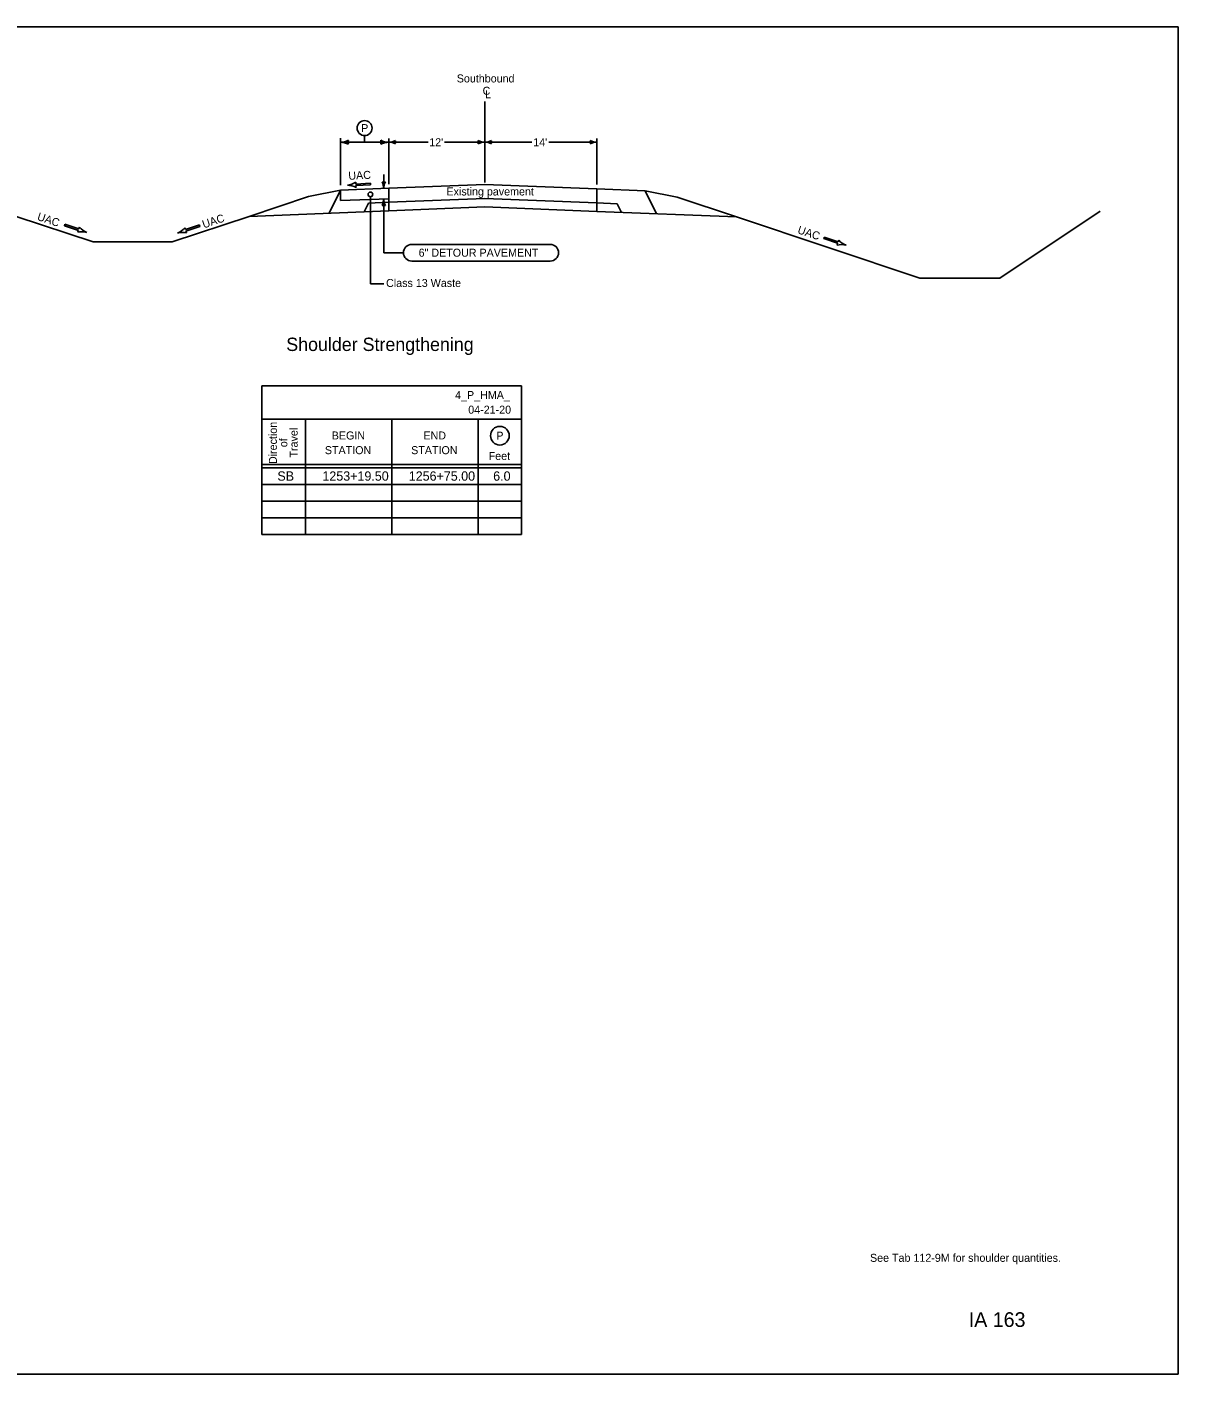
# Model space of a CAD drawing. Extents: x 10133 to 81668, y 7924 to 11018.
# Drawn here: x 11541 to 13268, y 7924 to 9944 of the extents above; entities that cross this region are included whole.
import ezdxf

# ---------------------------------------------------------------- set-up
doc = ezdxf.new("R2010")
doc.units = 0
for name, color, linetype in [('dsnCellElements', 7, 'Continuous'), ('dsnCellsNorthArrow', 7, 'Continuous'), ('DsnShtRevisedText', 7, 'Continuous'), ('dsnStdNameDate', 7, 'Continuous'), ('dsnStdTable', 7, 'Continuous'), ('dsnTextFinalPlan', 7, 'Continuous'), ('dsnTextTabulation', 7, 'Continuous'), ('dsnXsPCCPavementBottom', 7, 'Continuous'), ('dsnXsShldrEarthFill', 7, 'Continuous'), ('dsnXsShldrSpecialBackBottom', 7, 'Continuous'), ('Level 6', 7, 'Continuous'), ('Level 7', 7, 'Continuous'), ('Level 8', 7, 'Continuous'), ('SheetAddendum', 7, 'Continuous'), ('SheetBorder', 7, 'Continuous')]:
    doc.layers.add(name, color=color, linetype=linetype)

# ---------------------------------------------------------------- blocks, each defined once
blk = doc.blocks.new('LT')
at = {"layer": 'dsnCellsNorthArrow'}
for centre, radius, start, end in [((-35.6, 0), 16.4, 342.2666, 17.7333), ((0, 42.5), 42.5, 241.9275, 270), ((0, -42.5), 42.5, 90, 118.0725)]:
    blk.add_arc(centre, radius, start, end, dxfattribs=at)

msp = doc.modelspace()

# ---------------------------------------------------------------- linework, layer by layer
at = {"layer": 'DsnShtRevisedText'}
for p, q in [((12022, 9706.6), (12022, 9706.6)), ((12034.5, 9711.3), (12034.7, 9708.5)), ((12034.7, 9708.5), (12056.7, 9709.7)), ((12056.8, 9707.3), (12034.8, 9706.1)), ((12034.8, 9706.1), (12035, 9703.3)), ((12056.7, 9709.7), (12056.8, 9707.3)), ((12056.4, 9558.7), (12056.4, 9689.4)), ((12326.2, 9618), (12118.6, 9618)), ((12118.6, 9618), (12326.2, 9618)), ((12118.6, 9593), (12326.2, 9593)), ((12118.6, 9593), (12326.2, 9593)), ((12076.7, 9558.7), (12056.4, 9558.7))]:
    msp.add_line(p, q, dxfattribs=at)
msp.add_circle((12056.4, 9692.9), 3.5, dxfattribs=at)
for centre, radius, start, end in [((12019.5, 9732.3), 25.8, 275.5881, 305.6181), ((12022.4, 9680.8), 25.8, 60.854, 90.8841), ((12118.6, 9605.5), 12.5, 90, 270), ((12118.6, 9605.5), 12.5, 90, 270), ((12326.2, 9605.5), 12.5, 270, 90), ((12326.2, 9605.5), 12.5, 270, 90)]:
    msp.add_arc(centre, radius, start, end, dxfattribs=at)
at = {"layer": 'dsnStdNameDate'}
for p, q in [((12084, 9702.1), (12011.6, 9699.2)), ((12011.6, 9699.2), (12011.6, 9683.6)), ((12084, 9702.1), (12084, 9686.4)), ((12084, 9686.4), (12011.6, 9683.6))]:
    msp.add_line(p, q, dxfattribs=at)
at = {"layer": 'dsnStdTable'}
for p, q in [((11893.9, 9183.1), (11893.9, 9406.1)), ((11893.9, 9406.1), (12283.2, 9406.1)), ((12283.2, 9183.1), (12283.2, 9406.1)), ((11893.9, 9356.1), (12283.2, 9356.1)), ((11959.2, 9183.1), (11959.2, 9356.1)), ((12088.6, 9356.1), (12088.6, 9183.1)), ((12218.2, 9183.1), (12218.2, 9356.1)), ((11893.9, 9288.1), (12283.2, 9288.1)), ((11893.9, 9283.1), (12283.2, 9283.1)), ((11893.9, 9258.1), (12283.2, 9258.1)), ((11893.9, 9233.1), (12283.2, 9233.1)), ((11893.9, 9208.1), (12283.2, 9208.1)), ((11893.9, 9183.1), (12283.2, 9183.1))]:
    msp.add_line(p, q, dxfattribs=at)
at = {"layer": 'dsnTextFinalPlan'}
for p, q in [((12011.6, 9699.2), (12084, 9702.1)), ((12011.6, 9683.6), (12011.6, 9699.2)), ((12084, 9702.1), (12084, 9686.4)), ((12084, 9686.4), (12011.6, 9683.6))]:
    msp.add_line(p, q, dxfattribs=at)
at = {"layer": 'dsnXsPCCPavementBottom'}
for p, q in [((12084.1, 9668.4), (12084.1, 9702.1)), ((12396.1, 9667.4), (12396.1, 9701.1)), ((12084.1, 9668.4), (11874.9, 9660)), ((12396.1, 9667.4), (12605.2, 9659.1))]:
    msp.add_line(p, q, dxfattribs=at)
at = {"layer": 'dsnXsShldrEarthFill'}
for p, q in [((12011.6, 9699.2), (11963.6, 9689.6)), ((12468.5, 9698.2), (12516.5, 9688.6)), ((11963.6, 9689.6), (11874.9, 9660)), ((12516.5, 9688.6), (12605.2, 9659.1)), ((11525.2, 9660), (11641, 9621.9)), ((11874.9, 9660), (11759.1, 9621.9)), ((12605.2, 9659.1), (12880.2, 9567.4)), ((13000.2, 9567.4), (13150.7, 9667.7)), ((11598.5, 9648.2), (11597.8, 9645.9)), ((11597.8, 9645.9), (11618.7, 9638.9)), ((11619.4, 9641.2), (11598.5, 9648.2)), ((11618.7, 9638.9), (11617.8, 9636.3)), ((11620.3, 9643.9), (11619.4, 9641.2)), ((11631.1, 9636), (11631.1, 9636)), ((11778.2, 9642.8), (11779.1, 9640.2)), ((11779.1, 9640.2), (11800, 9647.1)), ((11800.7, 9644.8), (11779.9, 9637.9)), ((11779.9, 9637.9), (11780.7, 9635.2)), ((11800, 9647.1), (11800.7, 9644.8)), ((11640.9, 9621.9), (11759.1, 9621.9)), ((11767.4, 9635), (11767.4, 9635)), ((12737, 9628.8), (12736.3, 9626.6)), ((12736.3, 9626.6), (12757.1, 9619.6)), ((12757.9, 9621.9), (12737, 9628.8)), ((12757.1, 9619.6), (12756.2, 9616.9)), ((12758.8, 9624.5), (12757.9, 9621.9)), ((12769.6, 9616.7), (12769.6, 9616.7)), ((13000.2, 9567.4), (12880.2, 9567.4))]:
    msp.add_line(p, q, dxfattribs=at)
for centre, start, end in [((11624, 9611.2), 73.917, 103.947), ((11640.3, 9660.1), 219.183, 249.213), ((11758.2, 9659.1), 290.787, 320.817), ((11774.5, 9610.2), 76.053, 106.083), ((12762.5, 9591.9), 73.917, 103.947), ((12778.8, 9640.8), 219.183, 249.213)]:
    msp.add_arc(centre, 25.8, start, end, dxfattribs=at)
at = {"layer": 'dsnXsShldrSpecialBackBottom'}
for p, q in [((12053.6, 9679.9), (12047.1, 9666.9)), ((12084.1, 9681.1), (12053.6, 9679.9)), ((12396.1, 9680.1), (12426.5, 9678.9)), ((12426.5, 9678.9), (12433, 9665.9))]:
    msp.add_line(p, q, dxfattribs=at)
at = {"layer": 'Level 6'}
for p, q in [((12011.6, 9699.2), (11994.4, 9664.8)), ((12084.1, 9702.1), (12011.6, 9699.2)), ((12396.1, 9701.1), (12468.5, 9698.2)), ((12468.5, 9698.2), (12485.7, 9663.8))]:
    msp.add_line(p, q, dxfattribs=at)
at = {"layer": 'Level 7'}
for p, q in [((12084.1, 9702.1), (12228.1, 9707.8)), ((12228.1, 9707.8), (12396.1, 9701.1)), ((12396.1, 9680.1), (12396.1, 9701.1)), ((12084.1, 9681.1), (12228.1, 9686.8)), ((12228.1, 9686.8), (12396.1, 9680.1)), ((12084.1, 9668.4), (12228.1, 9674.1)), ((12228.1, 9674.1), (12396.1, 9667.4))]:
    msp.add_line(p, q, dxfattribs=at)
at = {"layer": 'Level 8'}
for p, q in [((12228, 9724.3), (12228, 9832.2)), ((12011.6, 9706.6), (12011.6, 9777.1)), ((12047.8, 9771.1), (12047.8, 9781.1)), ((12084, 9708.1), (12084, 9776.9)), ((12396, 9776.9), (12396, 9707.9)), ((12084, 9771.1), (12011.6, 9771.1)), ((12084, 9771.1), (12143.2, 9771.1)), ((12167.8, 9771.1), (12228, 9771.1)), ((12228, 9771.1), (12298.4, 9771.1)), ((12323.9, 9771.1), (12396, 9771.1)), ((12076.4, 9722.9), (12076.4, 9701.8)), ((12228.1, 9710.8), (12228.1, 9724.3)), ((12076.4, 9686.1), (12076.4, 9605.5)), ((12106.1, 9605.5), (12076.4, 9605.5))]:
    msp.add_line(p, q, dxfattribs=at)
for centre, radius in [((12047.8, 9792.3), 11.2), ((12250.6, 9331.1), 14)]:
    msp.add_circle(centre, radius, dxfattribs=at)
for centre, radius, start, end in [((12084, 9792.4), 21.3, 270, 298.0725), ((12084, 9749.9), 21.3, 61.9275, 90), ((12101.9, 9771.1), 8.21, 162.2666, 197.7334), ((12210.2, 9771.1), 8.21, 342.2666, 17.7334), ((12228, 9792.4), 21.3, 241.9275, 270), ((12228, 9749.9), 21.3, 90, 118.0725), ((12228, 9792.4), 21.3, 270, 298.0725), ((12228, 9749.9), 21.3, 61.9275, 90), ((12245.8, 9771.1), 8.21, 162.2666, 197.7334), ((12378.2, 9771.1), 8.21, 342.2666, 17.7334), ((12396, 9792.4), 21.3, 241.9275, 270), ((12396, 9749.9), 21.3, 90, 118.0725), ((12076.4, 9719.6), 8.21, 252.2666, 287.7334), ((12055.2, 9701.8), 21.3, 360, 28.0725), ((12097.7, 9701.8), 21.3, 151.9275, 180), ((12055.2, 9686.2), 21.3, 331.9275, 0), ((12076.4, 9668.3), 8.21, 72.2666, 107.7334), ((12097.7, 9686.2), 21.3, 180, 208.0725)]:
    msp.add_arc(centre, radius, start, end, dxfattribs=at)
at = {"layer": 'SheetBorder'}
msp.add_lwpolyline([(10132.5, 9944), (13267.5, 9944), (13267.5, 7924), (10132.5, 7924)], close=True, dxfattribs=at)

# ---------------------------------------------------------------- block references
at = {"layer": 'Level 8', "xscale": 0.5999999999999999, "yscale": 0.5999999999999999, "rotation": 180}
msp.add_blockref('LT', (12011.6, 9771.1), dxfattribs=at)
at = {"layer": 'Level 8', "xscale": 0.5999999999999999, "yscale": 0.5999999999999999}
msp.add_blockref('LT', (12084, 9771.1), dxfattribs=at)

# ---------------------------------------------------------------- texts
at = {"layer": 'dsnCellElements'}
msp.add_text('IA 163', height=22, dxfattribs=at).set_placement((12953.7, 7994.7))
at = {"layer": 'DsnShtRevisedText'}
msp.add_text('UAC', height=12, rotation=2.9216, dxfattribs=at).set_placement((12023.7, 9714.7))
for s, height, p in [('6" DETOUR PAVEMENT', 12, (12128.8, 9599.5)), ('Class 13 Waste', 12, (12080, 9554.1)), ('Shoulder Strengthening', 20, (11930.3, 9458.1)), ('See Tab 112-9M for shoulder quantities.', 12, (12805.6, 8092.3))]:
    msp.add_text(s, height=height, dxfattribs=at).set_placement(p)
at = {"layer": 'dsnStdTable'}
for s, p in [('Direction', (11916.3, 9288.6)), ('Travel', (11947.4, 9298.4)), ('of', (11931.9, 9313.8))]:
    msp.add_text(s, height=12, rotation=90, dxfattribs=at).set_placement(p)
for s, p in [('BEGIN', (11998.5, 9325.4)), ('END', (12136, 9325.4)), ('STATION', (11988.2, 9303.4)), ('STATION', (12117.6, 9303.4)), ('Feet', (12233.8, 9294.7))]:
    msp.add_text(s, height=12, dxfattribs=at).set_placement(p)
at = {"layer": 'dsnTextTabulation'}
for s, p in [('4_P_HMA_   ', (12183.5, 9386.1)), ('04-21-20', (12203.2, 9364.1))]:
    msp.add_text(s, height=12, dxfattribs=at).set_placement(p)
at = {"layer": 'dsnXsShldrEarthFill'}
for rotation, p in [(341.565, (11555.9, 9654.8)), (18.435, (11806.7, 9641.8)), (341.565, (12696, 9634.9))]:
    msp.add_text('UAC', height=12, rotation=rotation, dxfattribs=at).set_placement(p)
at = {"layer": 'Level 7'}
msp.add_text('Existing pavement', height=12, dxfattribs=at).set_placement((12170.5, 9691.3))
at = {"layer": 'Level 8'}
for s, p in [('Southbound', (12186, 9860.8)), ('C', (12224.7, 9842.3)), ('L', (12228.4, 9837.1)), ('P', (12042.6, 9786.3)), ("12'", (12144.7, 9765.1)), ("14'", (12300.7, 9765.1)), ('P', (12245.3, 9325.1))]:
    msp.add_text(s, height=12, dxfattribs=at).set_placement(p)
at = {"layer": 'SheetAddendum'}
for s, p in [('SB', (11917, 9263.6)), ('1253+19.50', (11984.5, 9263.6)), ('1256+75.00', (12114, 9263.6)), ('6.0', (12240.6, 9263.6))]:
    msp.add_text(s, height=14, dxfattribs=at).set_placement(p)

doc.saveas('drawing.dxf')
